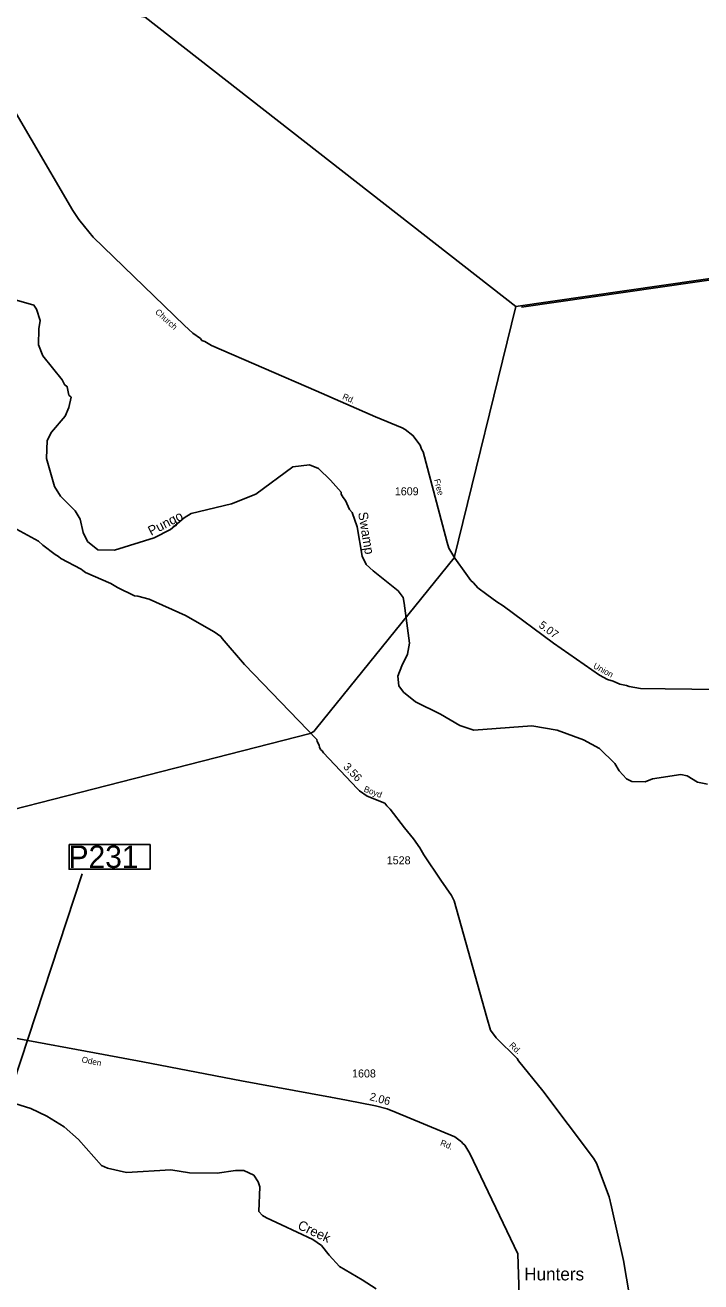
# Model space of a CAD drawing. Extents: x 2532689 to 2764727, y 536648 to 732970.
# Drawn here: x 2645127 to 2655684, y 653624 to 673249 of the extents above; entities that cross this region are included whole.
import ezdxf

# ---------------------------------------------------------------- set-up
doc = ezdxf.new("R2010")
doc.units = 0
for name, color, linetype in [('Exist Civil Demographics Community Label', 7, 'Continuous'), ('Exist Hydrographic Creek Single Shore', 7, 'Continuous'), ('Exist Hydrographic Creek Single Shore Label', 7, 'Continuous'), ('Exist Hydrographic Swamp Label', 7, 'Continuous'), ('Exist Road Secondary Mileage Hundredths English Label', 7, 'Continuous'), ('Exist Road Secondary Structure Pipe Number Label', 7, 'Continuous'), ('Exist Road Secondary Type 51 Attributed', 7, 'Continuous'), ('Exist Road Secondary Type 51 Label', 7, 'Continuous'), ('Exist Road Secondary Type 51 Number Label', 7, 'Continuous'), ('Exist Utilities Electrical Transmission Line', 7, 'Continuous')]:
    doc.layers.add(name, color=color, linetype=linetype)

msp = doc.modelspace()

# ---------------------------------------------------------------- linework, layer by layer
at = {"layer": 'Exist Hydrographic Creek Single Shore'}
msp.add_line((2652883, 668846), (2660568, 669948), dxfattribs=at)
for points in [[(2655789, 661398), (2655630, 661428), (2655470, 661527), (2655369, 661549), (2654929, 661479), (2654813, 661435), (2654605, 661439), (2654521, 661478), (2654410, 661602), (2654340, 661717), (2654102, 661954), (2653849, 662088), (2653437, 662239), (2653044, 662305), (2652137, 662242), (2651918, 662312), (2651614, 662490), (2651227, 662682), (2651040, 662835), (2650963, 662933), (2650951, 663084), (2651014, 663244), (2651102, 663428), (2651132, 663597), (2651051, 664221), (2651032, 664312), (2650955, 664417), (2650565, 664727), (2650454, 664824), (2650393, 664956), (2650316, 665413), (2650236, 665636), (2650194, 665683), (2650132, 665825), (2650098, 665873), (2650063, 665924), (2650063, 665957), (2649900, 666144), (2649713, 666324), (2649570, 666381), (2649312, 666350), (2648730, 665926), (2648350, 665776), (2647720, 665623), (2647613, 665553), (2647400, 665373), (2647144, 665242), (2646524, 665052), (2646265, 665055), (2646104, 665186), (2646034, 665325), (2645988, 665533), (2645910, 665664), (2645680, 665895), (2645585, 666042), (2645459, 666480), (2645469, 666763), (2645541, 666891), (2645752, 667145), (2645808, 667279), (2645846, 667438), (2645812, 667473), (2645784, 667603), (2645741, 667637), (2645706, 667712), (2645406, 668087), (2645336, 668255), (2645339, 668504), (2645361, 668637), (2645307, 668812), (2645264, 668876), (2644920, 668977)], [(2650612, 653516), (2650392, 653655), (2650038, 653863), (2649875, 654041), (2649755, 654190), (2649620, 654287), (2649132, 654516), (2648896, 654622), (2648836, 654662), (2648777, 654725), (2648793, 655110), (2648767, 655185), (2648698, 655290), (2648546, 655363), (2648413, 655361), (2648130, 655320), (2647696, 655328), (2647404, 655372), (2646713, 655331), (2646412, 655398), (2646319, 655440), (2645960, 655849), (2645739, 656044), (2645468, 656213), (2645216, 656331), (2644801, 656460)]]:
    msp.add_lwpolyline(points, dxfattribs=at)
at = {"layer": 'Exist Road Secondary Structure Pipe Number Label'}
msp.add_line((2644937, 656700), (2646016, 659994), dxfattribs=at)
msp.add_lwpolyline([(2645813, 660452), (2647079, 660452), (2647079, 660068), (2645813, 660068)], close=True, dxfattribs=at)
at = {"layer": 'Exist Road Secondary Type 51 Attributed'}
for points in [[(2644566, 672584), (2645871, 670356), (2645965, 670212), (2646057, 670102), (2646191, 669939), (2647615, 668560), (2647748, 668441), (2647868, 668354), (2647888, 668326), (2647933, 668307), (2648038, 668245), (2649672, 667537), (2650603, 667130), (2651019, 666961), (2651062, 666934), (2651186, 666841), (2651299, 666689), (2651321, 666629), (2651344, 666586), (2651369, 666509), (2651719, 665172), (2651749, 665084), (2651842, 664927), (2652014, 664684), (2652092, 664578), (2652133, 664539), (2652201, 664461), (2652343, 664356), (2652498, 664243), (2652597, 664181), (2653384, 663598), (2654101, 663100), (2654225, 663033), (2654316, 663005), (2654419, 662959), (2654521, 662935), (2654565, 662920), (2654742, 662890), (2655126, 662883), (2656379, 662870)], [(2644531, 665629), (2645337, 665189), (2645405, 665128), (2645594, 664981), (2645651, 664950), (2645685, 664921), (2646005, 664756), (2646027, 664732), (2646072, 664703), (2646466, 664528), (2646571, 664468), (2646838, 664336), (2646887, 664331), (2647063, 664283), (2647633, 664029), (2648081, 663773), (2648183, 663704), (2648203, 663672), (2648554, 663264), (2649685, 662092), (2649689, 662064), (2649722, 662007), (2649727, 661975), (2649744, 661938), (2649766, 661918), (2649789, 661883), (2650317, 661328), (2650351, 661291), (2650470, 661208), (2650745, 661101), (2650778, 661058), (2650831, 661005), (2651055, 660714), (2651197, 660542), (2651296, 660402), (2651355, 660291), (2651623, 659899), (2651787, 659656), (2651829, 659575), (2652343, 657752), (2652397, 657553), (2652486, 657433), (2652815, 657110), (2652836, 657077), (2653214, 656607), (2654006, 655554), (2654055, 655480), (2654251, 654950), (2654288, 654798), (2654477, 653956), (2654613, 653161)], [(2644627, 657490), (2644890, 657447), (2646351, 657177), (2646965, 657061), (2648508, 656765), (2649583, 656566), (2649900, 656511), (2650148, 656461), (2650603, 656372), (2650781, 656324), (2650922, 656268), (2651840, 655889), (2651903, 655842), (2651944, 655813), (2651967, 655784), (2651995, 655757), (2652074, 655628), (2652825, 654062), (2652867, 652776), (2652876, 652673)]]:
    msp.add_lwpolyline(points, dxfattribs=at)
at = {"layer": 'Exist Utilities Electrical Transmission Line'}
for points in [[(2652796, 668853), (2647001, 673375), (2646947, 673384), (2650007, 679263), (2650294, 679890), (2653369, 686741), (2654699, 689711)], [(2652796, 668853), (2658499, 669677), (2660074, 669901), (2660609, 669977), (2663000, 670312), (2663178, 670332), (2665760, 670709), (2666509, 665522)], [(2652796, 668853), (2651828, 664932), (2649677, 662270), (2649640, 662219), (2649582, 662188), (2640916, 659969)]]:
    msp.add_lwpolyline(points, dxfattribs=at)

# ---------------------------------------------------------------- texts
at = {"layer": 'Exist Civil Demographics Community Label'}
msp.add_text('Hunters', height=200, dxfattribs=at).set_placement((2652924, 653647))
at = {"layer": 'Exist Hydrographic Creek Single Shore Label'}
msp.add_text('Creek', height=150, rotation=334.789, dxfattribs=at).set_placement((2649372, 654458))
at = {"layer": 'Exist Hydrographic Swamp Label'}
for s, rotation, p in [('Pungo', 27.2399, (2647095, 665272)), ('Swamp', 279.5843, (2650328, 665635))]:
    msp.add_text(s, height=150, rotation=rotation, dxfattribs=at).set_placement(p)
at = {"layer": 'Exist Road Secondary Mileage Hundredths English Label'}
for s, rotation, p in [('5.07', 323.4903, (2653141, 663856)), ('3.56', 313.6194, (2650088, 661659)), ('2.06', 344.8325, (2650499, 656465))]:
    msp.add_text(s, height=125, rotation=rotation, dxfattribs=at).set_placement(p)
at = {"layer": 'Exist Road Secondary Structure Pipe Number Label'}
msp.add_text('P231', height=350, dxfattribs=at).set_placement((2645806, 660088))
at = {"layer": 'Exist Road Secondary Type 51 Label'}
for s, rotation, p in [('Church', 318.0645, (2647150, 668757)), ('Rd.', 336.3568, (2650075, 667415)), ('Free', 284.6583, (2651514, 666150)), ('Union', 331.445, (2653993, 663215)), ('Boyd', 338.8675, (2650410, 661284)), ('Rd.', 315.5874, (2652682, 657310)), ('Oden', 348.934, (2646004, 657053)), ('Rd.', 337.7813, (2651604, 655760))]:
    msp.add_text(s, height=95, rotation=rotation, dxfattribs=at).set_placement(p)
at = {"layer": 'Exist Road Secondary Type 51 Number Label'}
for s, p in [('1609', (2650903, 665907)), ('1528', (2650777, 660145)), ('1608', (2650235, 656816))]:
    msp.add_text(s, height=125, dxfattribs=at).set_placement(p)

doc.saveas('drawing.dxf')
